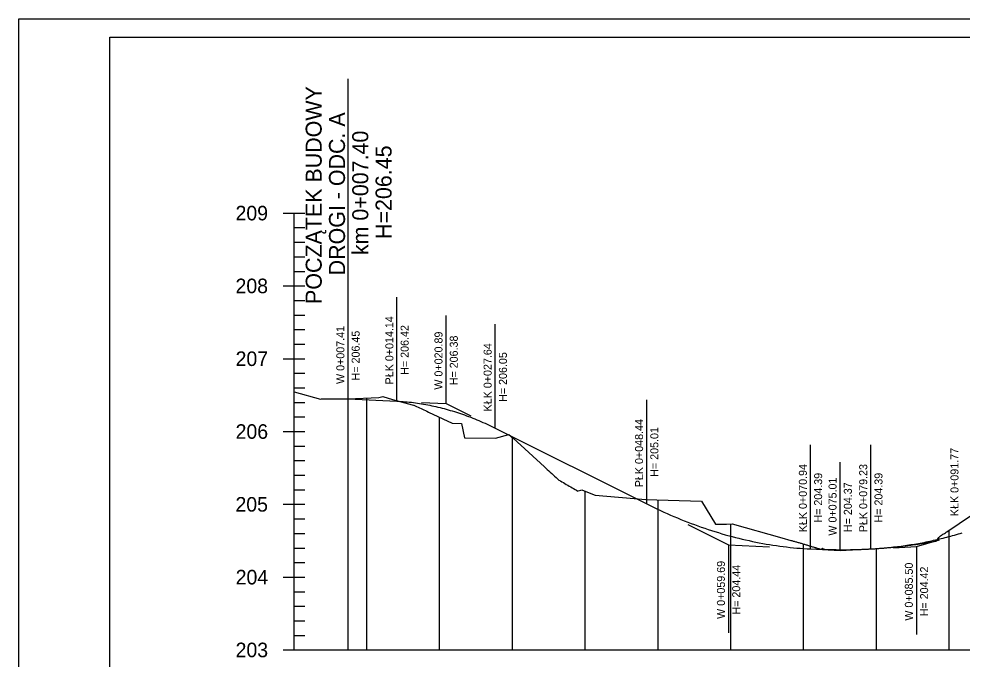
# Model space of a CAD drawing. Extents: x 6513080 to 6513380, y 6022307 to 6022459.
# Drawn here: x 6513079.9 to 6513209.5, y 6022367.3 to 6022455.2 of the extents above; entities that cross this region are included whole.
import ezdxf

# ---------------------------------------------------------------- set-up
doc = ezdxf.new("R2010")
doc.units = 0
for name, color, linetype in [('1', 7, 'Continuous'), ('42', 7, 'Continuous'), ('maxp_opisy', 7, 'Continuous'), ('maxp_ramka_2', 7, 'Continuous')]:
    doc.layers.add(name, color=color, linetype=linetype)

msp = doc.modelspace()

# ---------------------------------------------------------------- linework, layer by layer
for p, q in [((6513125.11, 6022403.07), (6513131.84, 6022402.73)), ((6513125.11, 6022403.07), (6513131.84, 6022402.73)), ((6513145.34, 6022399.02), (6513166.14, 6022388.62)), ((6513145.34, 6022399.02), (6513166.14, 6022388.62)), ((6513188.64, 6022382.43), (6513192.72, 6022382.23)), ((6513188.64, 6022382.43), (6513192.72, 6022382.23)), ((6513192.72, 6022382.23), (6513196.93, 6022382.44)), ((6513192.72, 6022382.23), (6513196.93, 6022382.44))]:
    msp.add_line(p, q)
for points in [[(6513131.84, 6022402.73), (6513132.12, 6022402.71), (6513132.41, 6022402.7), (6513132.69, 6022402.68), (6513132.97, 6022402.65), (6513133.25, 6022402.63), (6513133.53, 6022402.6), (6513133.81, 6022402.57), (6513134.09, 6022402.53), (6513134.37, 6022402.5), (6513134.65, 6022402.46), (6513134.94, 6022402.42), (6513135.22, 6022402.37), (6513135.5, 6022402.32), (6513135.78, 6022402.28), (6513136.06, 6022402.22), (6513136.34, 6022402.17), (6513136.62, 6022402.11), (6513136.9, 6022402.05), (6513137.19, 6022401.99), (6513137.47, 6022401.92), (6513137.75, 6022401.85), (6513138.03, 6022401.78), (6513138.31, 6022401.71), (6513138.87, 6022401.55), (6513139.15, 6022401.47), (6513139.43, 6022401.39), (6513139.72, 6022401.3), (6513140, 6022401.21), (6513140.28, 6022401.12), (6513140.56, 6022401.03), (6513140.84, 6022400.93), (6513141.12, 6022400.83), (6513141.4, 6022400.73), (6513141.68, 6022400.62), (6513141.97, 6022400.52), (6513142.25, 6022400.41), (6513142.53, 6022400.29), (6513142.81, 6022400.18), (6513143.09, 6022400.06), (6513143.37, 6022399.94), (6513143.65, 6022399.81), (6513143.93, 6022399.69), (6513144.21, 6022399.56), (6513144.5, 6022399.43), (6513144.78, 6022399.29), (6513145.06, 6022399.16), (6513145.34, 6022399.02)], [(6513131.84, 6022402.73), (6513132.12, 6022402.71), (6513132.41, 6022402.7), (6513132.69, 6022402.68), (6513132.97, 6022402.65), (6513133.25, 6022402.63), (6513133.53, 6022402.6), (6513133.81, 6022402.57), (6513134.09, 6022402.53), (6513134.37, 6022402.5), (6513134.65, 6022402.46), (6513134.94, 6022402.42), (6513135.22, 6022402.37), (6513135.5, 6022402.32), (6513135.78, 6022402.28), (6513136.06, 6022402.22), (6513136.34, 6022402.17), (6513136.62, 6022402.11), (6513136.9, 6022402.05), (6513137.19, 6022401.99), (6513137.47, 6022401.92), (6513137.75, 6022401.85), (6513138.03, 6022401.78), (6513138.31, 6022401.71), (6513138.87, 6022401.55), (6513139.15, 6022401.47), (6513139.43, 6022401.39), (6513139.72, 6022401.3), (6513140, 6022401.21), (6513140.28, 6022401.12), (6513140.56, 6022401.03), (6513140.84, 6022400.93), (6513141.12, 6022400.83), (6513141.4, 6022400.73), (6513141.68, 6022400.62), (6513141.97, 6022400.52), (6513142.25, 6022400.41), (6513142.53, 6022400.29), (6513142.81, 6022400.18), (6513143.09, 6022400.06), (6513143.37, 6022399.94), (6513143.65, 6022399.81), (6513143.93, 6022399.69), (6513144.21, 6022399.56), (6513144.5, 6022399.43), (6513144.78, 6022399.29), (6513145.06, 6022399.16), (6513145.34, 6022399.02)], [(6513166.14, 6022388.62), (6513166.61, 6022388.39), (6513167.08, 6022388.16), (6513167.55, 6022387.93), (6513168.02, 6022387.72), (6513168.49, 6022387.5), (6513168.96, 6022387.29), (6513169.42, 6022387.09), (6513169.89, 6022386.88), (6513170.36, 6022386.69), (6513170.83, 6022386.49), (6513171.3, 6022386.31), (6513171.77, 6022386.12), (6513172.24, 6022385.94), (6513172.7, 6022385.77), (6513173.17, 6022385.6), (6513173.64, 6022385.43), (6513174.11, 6022385.27), (6513174.58, 6022385.11), (6513175.05, 6022384.96), (6513175.52, 6022384.81), (6513175.99, 6022384.67), (6513176.45, 6022384.53), (6513176.92, 6022384.39), (6513177.86, 6022384.13), (6513178.33, 6022384.01), (6513178.8, 6022383.89), (6513179.27, 6022383.78), (6513179.73, 6022383.67), (6513180.2, 6022383.57), (6513180.67, 6022383.47), (6513181.14, 6022383.37), (6513181.61, 6022383.28), (6513182.08, 6022383.19), (6513182.55, 6022383.11), (6513183.01, 6022383.03), (6513183.48, 6022382.96), (6513183.95, 6022382.89), (6513184.42, 6022382.82), (6513184.89, 6022382.76), (6513185.36, 6022382.7), (6513185.83, 6022382.65), (6513186.29, 6022382.6), (6513186.76, 6022382.56), (6513187.23, 6022382.52), (6513187.7, 6022382.49), (6513188.17, 6022382.46), (6513188.64, 6022382.43)], [(6513166.14, 6022388.62), (6513166.61, 6022388.39), (6513167.08, 6022388.16), (6513167.55, 6022387.93), (6513168.02, 6022387.72), (6513168.49, 6022387.5), (6513168.96, 6022387.29), (6513169.42, 6022387.09), (6513169.89, 6022386.88), (6513170.36, 6022386.69), (6513170.83, 6022386.49), (6513171.3, 6022386.31), (6513171.77, 6022386.12), (6513172.24, 6022385.94), (6513172.7, 6022385.77), (6513173.17, 6022385.6), (6513173.64, 6022385.43), (6513174.11, 6022385.27), (6513174.58, 6022385.11), (6513175.05, 6022384.96), (6513175.52, 6022384.81), (6513175.99, 6022384.67), (6513176.45, 6022384.53), (6513176.92, 6022384.39), (6513177.86, 6022384.13), (6513178.33, 6022384.01), (6513178.8, 6022383.89), (6513179.27, 6022383.78), (6513179.73, 6022383.67), (6513180.2, 6022383.57), (6513180.67, 6022383.47), (6513181.14, 6022383.37), (6513181.61, 6022383.28), (6513182.08, 6022383.19), (6513182.55, 6022383.11), (6513183.01, 6022383.03), (6513183.48, 6022382.96), (6513183.95, 6022382.89), (6513184.42, 6022382.82), (6513184.89, 6022382.76), (6513185.36, 6022382.7), (6513185.83, 6022382.65), (6513186.29, 6022382.6), (6513186.76, 6022382.56), (6513187.23, 6022382.52), (6513187.7, 6022382.49), (6513188.17, 6022382.46), (6513188.64, 6022382.43)], [(6513196.93, 6022382.44), (6513197.19, 6022382.45), (6513197.45, 6022382.47), (6513197.71, 6022382.49), (6513197.97, 6022382.5), (6513198.24, 6022382.52), (6513198.5, 6022382.54), (6513198.76, 6022382.57), (6513199.02, 6022382.59), (6513199.28, 6022382.61), (6513199.54, 6022382.64), (6513199.8, 6022382.67), (6513200.06, 6022382.7), (6513200.33, 6022382.73), (6513200.59, 6022382.76), (6513200.85, 6022382.79), (6513201.11, 6022382.83), (6513201.37, 6022382.86), (6513201.63, 6022382.9), (6513201.89, 6022382.94), (6513202.15, 6022382.98), (6513202.42, 6022383.02), (6513202.68, 6022383.06), (6513202.94, 6022383.1), (6513203.46, 6022383.2), (6513203.72, 6022383.24), (6513203.98, 6022383.29), (6513204.24, 6022383.34), (6513204.51, 6022383.4), (6513204.77, 6022383.45), (6513205.03, 6022383.5), (6513205.29, 6022383.56), (6513205.55, 6022383.62), (6513205.81, 6022383.68), (6513206.07, 6022383.74), (6513206.34, 6022383.8), (6513206.6, 6022383.86), (6513206.86, 6022383.93), (6513207.12, 6022383.99), (6513207.38, 6022384.06), (6513207.64, 6022384.13), (6513207.9, 6022384.2), (6513208.16, 6022384.27), (6513208.43, 6022384.34), (6513208.69, 6022384.42), (6513208.95, 6022384.49), (6513209.21, 6022384.57), (6513209.47, 6022384.65)], [(6513196.93, 6022382.44), (6513197.19, 6022382.45), (6513197.45, 6022382.47), (6513197.71, 6022382.49), (6513197.97, 6022382.5), (6513198.24, 6022382.52), (6513198.5, 6022382.54), (6513198.76, 6022382.57), (6513199.02, 6022382.59), (6513199.28, 6022382.61), (6513199.54, 6022382.64), (6513199.8, 6022382.67), (6513200.06, 6022382.7), (6513200.33, 6022382.73), (6513200.59, 6022382.76), (6513200.85, 6022382.79), (6513201.11, 6022382.83), (6513201.37, 6022382.86), (6513201.63, 6022382.9), (6513201.89, 6022382.94), (6513202.15, 6022382.98), (6513202.42, 6022383.02), (6513202.68, 6022383.06), (6513202.94, 6022383.1), (6513203.46, 6022383.2), (6513203.72, 6022383.24), (6513203.98, 6022383.29), (6513204.24, 6022383.34), (6513204.51, 6022383.4), (6513204.77, 6022383.45), (6513205.03, 6022383.5), (6513205.29, 6022383.56), (6513205.55, 6022383.62), (6513205.81, 6022383.68), (6513206.07, 6022383.74), (6513206.34, 6022383.8), (6513206.6, 6022383.86), (6513206.86, 6022383.93), (6513207.12, 6022383.99), (6513207.38, 6022384.06), (6513207.64, 6022384.13), (6513207.9, 6022384.2), (6513208.16, 6022384.27), (6513208.43, 6022384.34), (6513208.69, 6022384.42), (6513208.95, 6022384.49), (6513209.21, 6022384.57), (6513209.47, 6022384.65)]]:
    msp.add_lwpolyline(points)
at = {"layer": '1'}
for p, q in [((6513116.2, 6022428.56), (6513119.2, 6022428.56)), ((6513116.2, 6022428.56), (6513119.2, 6022428.56)), ((6513117.7, 6022368.56), (6513117.7, 6022428.56)), ((6513117.7, 6022426.56), (6513119.2, 6022426.56)), ((6513117.7, 6022424.56), (6513119.2, 6022424.56)), ((6513117.7, 6022422.56), (6513119.2, 6022422.56)), ((6513117.7, 6022420.56), (6513119.2, 6022420.56)), ((6513116.2, 6022418.56), (6513119.2, 6022418.56)), ((6513117.7, 6022416.56), (6513119.2, 6022416.56)), ((6513117.7, 6022414.56), (6513119.2, 6022414.56)), ((6513117.7, 6022412.56), (6513119.2, 6022412.56)), ((6513117.7, 6022410.56), (6513119.2, 6022410.56)), ((6513116.2, 6022408.56), (6513119.2, 6022408.56)), ((6513117.7, 6022406.56), (6513119.2, 6022406.56)), ((6513117.7, 6022404.56), (6513119.2, 6022404.56)), ((6513117.7, 6022402.56), (6513119.2, 6022402.56)), ((6513127.7, 6022368.56), (6513127.7, 6022403.19)), ((6513135.22, 6022402.56), (6513138.59, 6022402.39)), ((6513138.59, 6022402.39), (6513141.97, 6022400.71)), ((6513117.7, 6022400.56), (6513119.2, 6022400.56)), ((6513137.7, 6022368.56), (6513137.7, 6022400.53)), ((6513116.2, 6022398.56), (6513119.2, 6022398.56)), ((6513147.7, 6022368.56), (6513147.7, 6022397.7)), ((6513117.7, 6022396.56), (6513119.2, 6022396.56)), ((6513117.7, 6022394.56), (6513119.2, 6022394.56)), ((6513117.7, 6022392.56), (6513119.2, 6022392.56)), ((6513117.7, 6022390.56), (6513119.2, 6022390.56)), ((6513157.7, 6022368.56), (6513157.7, 6022390.34)), ((6513167.7, 6022368.56), (6513167.7, 6022389.18)), ((6513116.2, 6022388.56), (6513119.2, 6022388.56)), ((6513117.7, 6022386.56), (6513119.2, 6022386.56)), ((6513171.77, 6022385.81), (6513177.39, 6022383)), ((6513177.7, 6022368.56), (6513177.7, 6022385.87)), ((6513117.7, 6022384.56), (6513119.2, 6022384.56)), ((6513207.7, 6022368.56), (6513207.7, 6022385)), ((6513117.7, 6022382.56), (6513119.2, 6022382.56)), ((6513177.39, 6022383), (6513183.01, 6022382.71)), ((6513187.7, 6022368.56), (6513187.7, 6022383.11)), ((6513200.06, 6022382.6), (6513203.2, 6022382.76)), ((6513203.2, 6022382.76), (6513206.34, 6022383.7)), ((6513197.7, 6022368.56), (6513197.7, 6022382.49)), ((6513117.7, 6022380.56), (6513119.2, 6022380.56)), ((6513116.2, 6022378.56), (6513119.2, 6022378.56)), ((6513117.7, 6022376.56), (6513119.2, 6022376.56)), ((6513117.7, 6022374.56), (6513119.2, 6022374.56)), ((6513117.7, 6022372.56), (6513119.2, 6022372.56)), ((6513117.7, 6022370.56), (6513119.2, 6022370.56)), ((6513117.7, 6022368.56), (6513117.7, 6022370.56)), ((6513127.7, 6022368.56), (6513127.7, 6022369.56)), ((6513137.7, 6022368.56), (6513137.7, 6022369.56)), ((6513147.7, 6022368.56), (6513147.7, 6022369.56)), ((6513157.7, 6022368.56), (6513157.7, 6022369.56)), ((6513167.7, 6022368.56), (6513167.7, 6022369.56)), ((6513177.7, 6022368.56), (6513177.7, 6022369.56)), ((6513187.7, 6022368.56), (6513187.7, 6022369.56)), ((6513197.7, 6022368.56), (6513197.7, 6022369.56)), ((6513207.7, 6022368.56), (6513207.7, 6022369.56)), ((6513116.2, 6022368.56), (6513119.2, 6022368.56)), ((6513117.7, 6022368.56), (6513327.7, 6022368.56))]:
    msp.add_line(p, q, dxfattribs=at)
msp.add_lwpolyline([(6513117.7, 6022403.99), (6513121.32, 6022402.99), (6513121.46, 6022403.07), (6513123.13, 6022403.04), (6513125.08, 6022403.07), (6513129.34, 6022403.24), (6513129.9, 6022403.38), (6513131.2, 6022402.95), (6513133.93, 6022402.23), (6513134.09, 6022402.19), (6513134.13, 6022402.17), (6513134.33, 6022402.08), (6513134.53, 6022401.99), (6513134.74, 6022401.89), (6513134.94, 6022401.8), (6513135.14, 6022401.71), (6513135.34, 6022401.62), (6513135.54, 6022401.52), (6513135.74, 6022401.43), (6513135.94, 6022401.34), (6513136.15, 6022401.24), (6513139.43, 6022399.72), (6513140.7, 6022399.68), (6513141.13, 6022397.7), (6513145.35, 6022397.63), (6513147.18, 6022398.17), (6513147.78, 6022397.63), (6513152.08, 6022393.69), (6513152.28, 6022393.51), (6513152.48, 6022393.33), (6513152.69, 6022393.15), (6513152.89, 6022392.96), (6513153.09, 6022392.78), (6513153.29, 6022392.6), (6513153.49, 6022392.42), (6513153.69, 6022392.24), (6513153.89, 6022392.06), (6513154.03, 6022391.94), (6513154.09, 6022391.9), (6513154.29, 6022391.78), (6513154.49, 6022391.66), (6513154.7, 6022391.54), (6513154.9, 6022391.42), (6513155.1, 6022391.3), (6513155.3, 6022391.18), (6513155.5, 6022391.07), (6513155.7, 6022390.95), (6513155.9, 6022390.84), (6513156.1, 6022390.72), (6513156.3, 6022390.61), (6513156.5, 6022390.5), (6513156.69, 6022390.39), (6513156.71, 6022390.4), (6513156.91, 6022390.45), (6513157.11, 6022390.5), (6513157.22, 6022390.53), (6513157.31, 6022390.49), (6513159.07, 6022389.82), (6513166.02, 6022389.23), (6513173.68, 6022388.98), (6513175.61, 6022385.83), (6513177.11, 6022385.82), (6513177.88, 6022385.89), (6513184.7, 6022383.94), (6513185.95, 6022383.61), (6513186.06, 6022383.58), (6513186.17, 6022383.55), (6513186.28, 6022383.52), (6513186.39, 6022383.49), (6513186.5, 6022383.46), (6513186.61, 6022383.43), (6513186.72, 6022383.4), (6513186.83, 6022383.36), (6513186.94, 6022383.33), (6513187.05, 6022383.3), (6513187.16, 6022383.27), (6513187.27, 6022383.24), (6513187.38, 6022383.21), (6513187.49, 6022383.18), (6513187.6, 6022383.14), (6513187.71, 6022383.11), (6513187.82, 6022383.08), (6513187.93, 6022383.05), (6513188.04, 6022383.01), (6513188.15, 6022382.98), (6513188.25, 6022382.95), (6513188.36, 6022382.91), (6513188.47, 6022382.88), (6513188.58, 6022382.85), (6513188.69, 6022382.81), (6513188.8, 6022382.78), (6513188.91, 6022382.74), (6513189.02, 6022382.71), (6513189.13, 6022382.68), (6513189.24, 6022382.64), (6513189.35, 6022382.61), (6513189.37, 6022382.6), (6513189.46, 6022382.58), (6513189.57, 6022382.54), (6513189.68, 6022382.51), (6513189.79, 6022382.48), (6513189.9, 6022382.45), (6513190.01, 6022382.42), (6513190.05, 6022382.41), (6513190.12, 6022382.4), (6513190.14, 6022382.4), (6513190.23, 6022382.51), (6513190.28, 6022382.56), (6513190.34, 6022382.49), (6513190.44, 6022382.38), (6513190.45, 6022382.38), (6513190.56, 6022382.38), (6513190.67, 6022382.37), (6513190.78, 6022382.37), (6513190.89, 6022382.37), (6513191, 6022382.36), (6513191.11, 6022382.36), (6513191.22, 6022382.36), (6513191.33, 6022382.35), (6513191.44, 6022382.35), (6513191.55, 6022382.35), (6513191.66, 6022382.34), (6513191.77, 6022382.34), (6513191.88, 6022382.34), (6513191.99, 6022382.34), (6513192.1, 6022382.34), (6513192.21, 6022382.33), (6513192.32, 6022382.33), (6513192.43, 6022382.33), (6513192.54, 6022382.33), (6513192.65, 6022382.33), (6513192.76, 6022382.33), (6513192.87, 6022382.33), (6513192.98, 6022382.33), (6513193.09, 6022382.33), (6513193.2, 6022382.33), (6513193.31, 6022382.33), (6513193.42, 6022382.33), (6513193.53, 6022382.33), (6513193.64, 6022382.33), (6513193.75, 6022382.33), (6513193.86, 6022382.33), (6513193.97, 6022382.33), (6513194.08, 6022382.33), (6513194.19, 6022382.34), (6513194.3, 6022382.34), (6513194.41, 6022382.34), (6513194.52, 6022382.34), (6513194.63, 6022382.34), (6513194.74, 6022382.35), (6513194.85, 6022382.35), (6513194.96, 6022382.35), (6513195.07, 6022382.36), (6513195.18, 6022382.36), (6513195.29, 6022382.36), (6513195.4, 6022382.37), (6513195.51, 6022382.37), (6513195.62, 6022382.37), (6513195.73, 6022382.38), (6513195.84, 6022382.38), (6513195.95, 6022382.39), (6513196.06, 6022382.39), (6513196.17, 6022382.4), (6513196.28, 6022382.4), (6513196.39, 6022382.41), (6513196.5, 6022382.41), (6513196.61, 6022382.42), (6513196.72, 6022382.43), (6513196.83, 6022382.43), (6513196.94, 6022382.44), (6513197.05, 6022382.44), (6513197.16, 6022382.45), (6513197.27, 6022382.46), (6513197.38, 6022382.47), (6513197.49, 6022382.47), (6513197.6, 6022382.48), (6513197.71, 6022382.49), (6513197.82, 6022382.5), (6513197.93, 6022382.5), (6513198.04, 6022382.51), (6513198.15, 6022382.52), (6513198.26, 6022382.53), (6513198.37, 6022382.54), (6513198.48, 6022382.55), (6513198.59, 6022382.55), (6513198.7, 6022382.56), (6513198.81, 6022382.57), (6513198.92, 6022382.58), (6513199.03, 6022382.59), (6513199.14, 6022382.6), (6513199.25, 6022382.61), (6513199.36, 6022382.62), (6513199.47, 6022382.63), (6513199.58, 6022382.64), (6513199.69, 6022382.65), (6513199.8, 6022382.66), (6513199.91, 6022382.68), (6513200.02, 6022382.69), (6513200.13, 6022382.7), (6513200.24, 6022382.71), (6513200.35, 6022382.72), (6513200.46, 6022382.73), (6513200.57, 6022382.74), (6513200.68, 6022382.76), (6513200.79, 6022382.77), (6513200.9, 6022382.78), (6513201.01, 6022382.79), (6513201.12, 6022382.81), (6513201.23, 6022382.82), (6513201.34, 6022382.83), (6513201.45, 6022382.85), (6513201.56, 6022382.86), (6513201.67, 6022382.87), (6513201.78, 6022382.89), (6513201.89, 6022382.9), (6513202, 6022382.92), (6513202.11, 6022382.93), (6513202.22, 6022382.94), (6513202.33, 6022382.96), (6513202.44, 6022382.97), (6513202.55, 6022382.99), (6513202.66, 6022383), (6513202.77, 6022383.02), (6513202.88, 6022383.03), (6513202.99, 6022383.05), (6513203.1, 6022383.06), (6513203.21, 6022383.08), (6513203.32, 6022383.1), (6513203.43, 6022383.11), (6513203.54, 6022383.13), (6513203.65, 6022383.14), (6513203.76, 6022383.16), (6513203.87, 6022383.18), (6513203.98, 6022383.19), (6513204.09, 6022383.21), (6513204.2, 6022383.23), (6513204.31, 6022383.25), (6513204.42, 6022383.26), (6513204.53, 6022383.28), (6513204.64, 6022383.3), (6513204.75, 6022383.32), (6513204.86, 6022383.33), (6513204.97, 6022383.35), (6513205.08, 6022383.37), (6513205.19, 6022383.39), (6513205.3, 6022383.41), (6513205.41, 6022383.42), (6513205.52, 6022383.44), (6513205.63, 6022383.46), (6513205.74, 6022383.48), (6513205.85, 6022383.5), (6513205.9, 6022383.51), (6513205.96, 6022383.58), (6513206.07, 6022383.72), (6513206.18, 6022383.85), (6513206.29, 6022383.99), (6513206.4, 6022384.14), (6513206.46, 6022384.21), (6513206.51, 6022384.24), (6513206.62, 6022384.31), (6513206.73, 6022384.37), (6513206.84, 6022384.44), (6513206.95, 6022384.5), (6513207.06, 6022384.57), (6513207.17, 6022384.64), (6513207.28, 6022384.72), (6513207.39, 6022384.79), (6513214.28, 6022389.47)], dxfattribs=at)
at = {"layer": '42'}
for p, q in [((6513125.11, 6022368.57), (6513125.11, 6022446.98)), ((6513131.84, 6022402.73), (6513131.84, 6022417.03)), ((6513125.11, 6022403.07), (6513125.11, 6022415.17)), ((6513125.11, 6022403.06), (6513125.11, 6022415.16)), ((6513138.59, 6022402.39), (6513138.59, 6022414.49)), ((6513145.34, 6022399.02), (6513145.34, 6022413.32)), ((6513125.11, 6022403.07), (6513131.84, 6022402.73)), ((6513166.14, 6022388.62), (6513166.14, 6022402.92)), ((6513145.34, 6022399.02), (6513166.14, 6022388.62)), ((6513188.64, 6022382.43), (6513188.64, 6022396.73)), ((6513196.93, 6022382.44), (6513196.93, 6022396.74)), ((6513192.72, 6022382.23), (6513192.72, 6022394.33)), ((6513177.39, 6022383), (6513177.39, 6022370.9)), ((6513203.2, 6022382.76), (6513203.2, 6022370.66)), ((6513188.64, 6022382.43), (6513192.72, 6022382.23)), ((6513192.72, 6022382.23), (6513196.93, 6022382.44))]:
    msp.add_line(p, q, dxfattribs=at)
for points in [[(6513131.84, 6022402.73), (6513132.12, 6022402.71), (6513132.41, 6022402.7), (6513132.69, 6022402.68), (6513132.97, 6022402.65), (6513133.25, 6022402.63), (6513133.53, 6022402.6), (6513133.81, 6022402.57), (6513134.09, 6022402.53), (6513134.37, 6022402.5), (6513134.65, 6022402.46), (6513134.94, 6022402.42), (6513135.22, 6022402.37), (6513135.5, 6022402.32), (6513135.78, 6022402.28), (6513136.06, 6022402.22), (6513136.34, 6022402.17), (6513136.62, 6022402.11), (6513136.9, 6022402.05), (6513137.19, 6022401.99), (6513137.47, 6022401.92), (6513137.75, 6022401.85), (6513138.03, 6022401.78), (6513138.31, 6022401.71), (6513138.87, 6022401.55), (6513139.15, 6022401.47), (6513139.43, 6022401.39), (6513139.72, 6022401.3), (6513140, 6022401.21), (6513140.28, 6022401.12), (6513140.56, 6022401.03), (6513140.84, 6022400.93), (6513141.12, 6022400.83), (6513141.4, 6022400.73), (6513141.68, 6022400.62), (6513141.97, 6022400.52), (6513142.25, 6022400.41), (6513142.53, 6022400.29), (6513142.81, 6022400.18), (6513143.09, 6022400.06), (6513143.37, 6022399.94), (6513143.65, 6022399.81), (6513143.93, 6022399.69), (6513144.21, 6022399.56), (6513144.5, 6022399.43), (6513144.78, 6022399.29), (6513145.06, 6022399.16), (6513145.34, 6022399.02)], [(6513166.14, 6022388.62), (6513166.61, 6022388.39), (6513167.08, 6022388.16), (6513167.55, 6022387.93), (6513168.02, 6022387.72), (6513168.49, 6022387.5), (6513168.96, 6022387.29), (6513169.42, 6022387.09), (6513169.89, 6022386.88), (6513170.36, 6022386.69), (6513170.83, 6022386.49), (6513171.3, 6022386.31), (6513171.77, 6022386.12), (6513172.24, 6022385.94), (6513172.7, 6022385.77), (6513173.17, 6022385.6), (6513173.64, 6022385.43), (6513174.11, 6022385.27), (6513174.58, 6022385.11), (6513175.05, 6022384.96), (6513175.52, 6022384.81), (6513175.99, 6022384.67), (6513176.45, 6022384.53), (6513176.92, 6022384.39), (6513177.86, 6022384.13), (6513178.33, 6022384.01), (6513178.8, 6022383.89), (6513179.27, 6022383.78), (6513179.73, 6022383.67), (6513180.2, 6022383.57), (6513180.67, 6022383.47), (6513181.14, 6022383.37), (6513181.61, 6022383.28), (6513182.08, 6022383.19), (6513182.55, 6022383.11), (6513183.01, 6022383.03), (6513183.48, 6022382.96), (6513183.95, 6022382.89), (6513184.42, 6022382.82), (6513184.89, 6022382.76), (6513185.36, 6022382.7), (6513185.83, 6022382.65), (6513186.29, 6022382.6), (6513186.76, 6022382.56), (6513187.23, 6022382.52), (6513187.7, 6022382.49), (6513188.17, 6022382.46), (6513188.64, 6022382.43)], [(6513196.93, 6022382.44), (6513197.19, 6022382.45), (6513197.45, 6022382.47), (6513197.71, 6022382.49), (6513197.97, 6022382.5), (6513198.24, 6022382.52), (6513198.5, 6022382.54), (6513198.76, 6022382.57), (6513199.02, 6022382.59), (6513199.28, 6022382.61), (6513199.54, 6022382.64), (6513199.8, 6022382.67), (6513200.06, 6022382.7), (6513200.33, 6022382.73), (6513200.59, 6022382.76), (6513200.85, 6022382.79), (6513201.11, 6022382.83), (6513201.37, 6022382.86), (6513201.63, 6022382.9), (6513201.89, 6022382.94), (6513202.15, 6022382.98), (6513202.42, 6022383.02), (6513202.68, 6022383.06), (6513202.94, 6022383.1), (6513203.46, 6022383.2), (6513203.72, 6022383.24), (6513203.98, 6022383.29), (6513204.24, 6022383.34), (6513204.51, 6022383.4), (6513204.77, 6022383.45), (6513205.03, 6022383.5), (6513205.29, 6022383.56), (6513205.55, 6022383.62), (6513205.81, 6022383.68), (6513206.07, 6022383.74), (6513206.34, 6022383.8), (6513206.6, 6022383.86), (6513206.86, 6022383.93), (6513207.12, 6022383.99), (6513207.38, 6022384.06), (6513207.64, 6022384.13), (6513207.9, 6022384.2), (6513208.16, 6022384.27), (6513208.43, 6022384.34), (6513208.69, 6022384.42), (6513208.95, 6022384.49), (6513209.21, 6022384.57), (6513209.47, 6022384.65)]]:
    msp.add_lwpolyline(points, dxfattribs=at)
at = {"layer": 'maxp_ramka_2'}
for points in [[(6513079.9, 6022455.24), (6513379.9, 6022455.24), (6513379.9, 6022306.74), (6513079.9, 6022306.74)], [(6513092.4, 6022309.24), (6513092.4, 6022452.74), (6513377.4, 6022452.74), (6513377.4, 6022309.24)]]:
    msp.add_lwpolyline(points, close=True, dxfattribs=at)

# ---------------------------------------------------------------- texts
at = {"layer": '1'}
for s, p in [('209', (6513109.66, 6022427.56)), ('209', (6513109.66, 6022427.56)), ('208', (6513109.66, 6022417.56)), ('207', (6513109.67, 6022407.56)), ('206', (6513109.67, 6022397.56)), ('205', (6513109.65, 6022387.56)), ('204', (6513109.68, 6022377.56)), ('203', (6513109.67, 6022367.56))]:
    msp.add_text(s, height=2, dxfattribs=at).set_placement(p)
at = {"layer": '42'}
for s, p in [('PŁK 0+014.14', (6513131.34, 6022405.03)), ('W 0+007.41', (6513124.61, 6022405.09)), ('H= 206.45', (6513126.71, 6022405.58)), ('H= 206.42', (6513133.44, 6022406.35)), ('W 0+020.89', (6513138.09, 6022404.31)), ('H= 206.38', (6513140.19, 6022404.91)), ('KŁK 0+027.64', (6513144.84, 6022401.32)), ('H= 206.05', (6513146.94, 6022402.63)), ('PŁK 0+048.44', (6513165.64, 6022390.91)), ('H= 205.01', (6513167.74, 6022392.34)), ('KŁK 0+091.77', (6513208.97, 6022386.94)), ('KŁK 0+070.94', (6513188.14, 6022384.73)), ('PŁK 0+079.23', (6513196.43, 6022384.73)), ('H= 204.39', (6513190.24, 6022386.05)), ('W 0+075.01', (6513192.22, 6022384.26)), ('H= 204.39', (6513198.53, 6022386.06)), ('H= 204.37', (6513194.32, 6022384.75)), ('W 0+059.69', (6513176.89, 6022372.82)), ('H= 204.44', (6513178.99, 6022373.42)), ('W 0+085.50', (6513202.7, 6022372.58)), ('H= 204.42', (6513204.8, 6022373.18))]:
    msp.add_text(s, height=1.1, rotation=90, dxfattribs=at).set_placement(p)
at = {"layer": 'maxp_opisy'}
for s, p in [('POCZĄTEK BUDOWY', (6513121.5, 6022416.08)), ('DROGI - ODC. A', (6513124.7, 6022420.01)), ('km 0+007.40', (6513127.9, 6022422.79)), ('H=206.45', (6513131.1, 6022425.01))]:
    msp.add_text(s, height=2.2, rotation=90.0162, dxfattribs=at).set_placement(p)

doc.saveas('drawing.dxf')
